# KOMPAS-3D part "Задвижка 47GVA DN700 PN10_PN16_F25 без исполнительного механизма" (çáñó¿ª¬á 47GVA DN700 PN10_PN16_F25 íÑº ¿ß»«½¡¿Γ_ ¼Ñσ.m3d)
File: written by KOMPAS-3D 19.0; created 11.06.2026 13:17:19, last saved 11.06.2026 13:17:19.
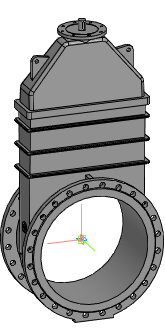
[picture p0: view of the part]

Document properties: Автор: Евгений; Полное имя файла: Z:\3.Личные\kachalov\001_3d для проектировщиков\2.2 Тип 47GVA, 47GVA.Z\_stp\_stp_Задвижка 47GVA DN40-DN1000 без исп.мех\Задвижка 47GVA DN700 PN10_PN16_F25 без исполнит_ мех.m3d

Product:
- Part/product: Задвижка 47GVA DN700 PN10_PN16_F25 без исполнительного механизма

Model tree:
1. Операция без истории:1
